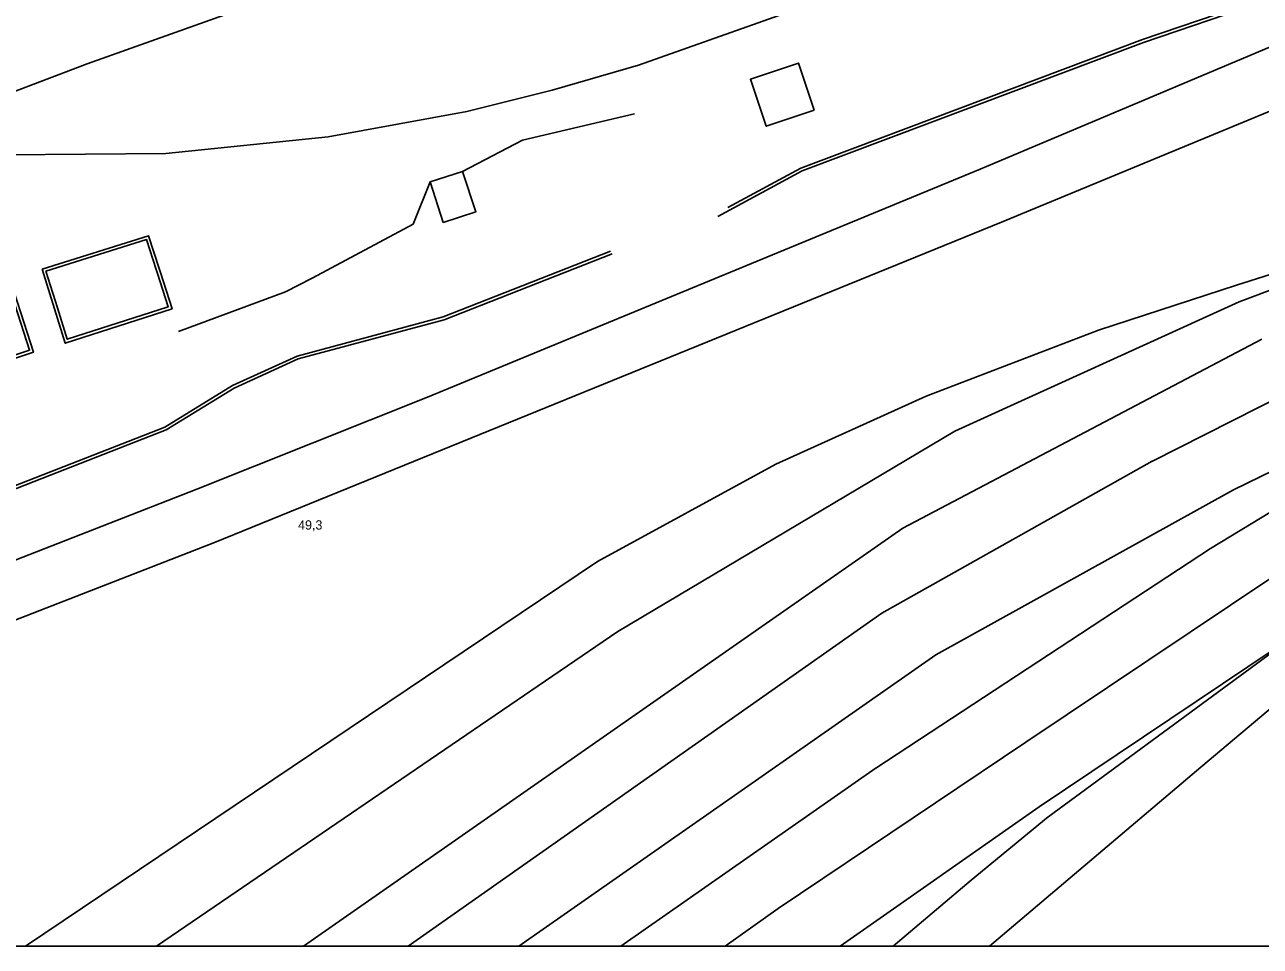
# Model space of a CAD drawing. Extents: x -932734 to -932083, y -737151 to -736752.
# Drawn here: x -932490.18 to -932480.24, y -736822.8 to -736815.38 of the extents above; entities that cross this region are included whole.
import ezdxf

# ---------------------------------------------------------------- set-up
doc = ezdxf.new("R2010")
doc.units = 0
for name, color, linetype in [('BorderBW', 7, 'Continuous'), ('Koleje_stávající', 7, 'Continuous'), ('Objekty_stávající', 7, 'Continuous'), ('SL_24_VODOVOD_PITNA', 7, 'Continuous'), ('WA_34_SCHODISTE', 7, 'Continuous'), ('WA_40_APARATY', 7, 'Continuous'), ('WA_46_TEXT', 7, 'Continuous')]:
    doc.layers.add(name, color=color, linetype=linetype)

# ---------------------------------------------------------------- blocks, each defined once
blk = doc.blocks.new('přehledka_1')
at = {"layer": 'BorderBW'}
for points in [[(0.07038371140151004, -0.048167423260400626), (0.07095589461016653, -0.050037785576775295), (0.06909275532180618, -0.05067112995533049), (0.06359666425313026, -0.05273965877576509), (0.06223989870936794, -0.053472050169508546)], [(0.06240033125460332, -0.053327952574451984), (0.063575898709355, -0.052694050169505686), (0.06907589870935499, -0.050624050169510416), (0.07089389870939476, -0.05000605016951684), (0.0703358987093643, -0.04818205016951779)], [(0.03090050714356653, -0.06521838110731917), (0.031617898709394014, -0.06500205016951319), (0.03645989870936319, -0.06340205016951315), (0.03973589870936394, -0.06237805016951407), (0.04277589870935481, -0.06099205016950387), (0.0433238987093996, -0.06076405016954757), (0.04648389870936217, -0.05954405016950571), (0.04893789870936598, -0.05858005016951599), (0.053337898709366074, -0.05686205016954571), (0.054429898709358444, -0.05619405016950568), (0.0554698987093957, -0.055718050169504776), (0.057817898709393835, -0.0550900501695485), (0.06051068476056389, -0.05402889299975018)], [(0.06054032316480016, -0.05407095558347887), (0.057833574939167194, -0.05513761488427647), (0.055486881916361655, -0.05576526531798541), (0.05445343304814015, -0.056238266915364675), (0.053360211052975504, -0.05690701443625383), (0.048956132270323, -0.05862660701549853), (0.046502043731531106, -0.05959064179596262), (0.04334250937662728, -0.06081046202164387), (0.04279587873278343, -0.06103789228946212), (0.03975379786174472, -0.06242484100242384), (0.03647520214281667, -0.0634496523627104), (0.03163296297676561, -0.06504973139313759), (0.031073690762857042, -0.06521838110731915)]]:
    blk.add_lwpolyline(points, dxfattribs=at)
at = {"layer": 'Koleje_stávající'}
for points in [[(0.05142461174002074, -0.05435464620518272), (0.051609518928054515, -0.054943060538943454), (0.05176850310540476, -0.05544901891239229), (0.05339300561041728, -0.05492577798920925), (0.05322057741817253, -0.05438935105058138), (0.05319975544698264, -0.05432454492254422), (0.05304550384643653, -0.05384465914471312)], [(0.0508118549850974, -0.05454069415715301), (0.05066389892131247, -0.05458770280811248), (0.04919491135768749, -0.05505449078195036), (0.04938414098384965, -0.05564069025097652), (0.04955197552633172, -0.05616065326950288), (0.05116111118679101, -0.055624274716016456), (0.050971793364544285, -0.0550374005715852)]]:
    blk.add_lwpolyline(points, close=True, dxfattribs=at)
at = {"layer": 'Objekty_stávající'}
for points in [[(0.03445734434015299, -0.06521838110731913), (0.036093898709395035, -0.06463005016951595), (0.04202189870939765, -0.06243405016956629), (0.0462318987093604, -0.06083805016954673), (0.053853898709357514, -0.05786005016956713), (0.057567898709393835, -0.05638005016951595), (0.06646389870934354, -0.05271205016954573), (0.07220389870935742, -0.050292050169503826), (0.07886789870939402, -0.04748005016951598), (0.0843098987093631, -0.045184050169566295), (0.08998389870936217, -0.042780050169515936), (0.0970738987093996, -0.03980405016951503), (0.09991516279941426, -0.03862719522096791)], [(0.03707951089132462, -0.06521838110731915), (0.0423098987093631, -0.06328005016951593), (0.0465698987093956, -0.06166605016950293), (0.05413589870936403, -0.05872005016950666), (0.06680589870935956, -0.053566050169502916), (0.07260589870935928, -0.05116405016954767), (0.0793358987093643, -0.04839405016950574), (0.08490189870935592, -0.04613605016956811), (0.09028589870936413, -0.044012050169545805), (0.0972998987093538, -0.041326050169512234), (0.09991516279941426, -0.0403290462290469)], [(0.04213989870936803, -0.05143205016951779), (0.04510189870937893, -0.05187005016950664), (0.04724389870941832, -0.05218205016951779), (0.050767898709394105, -0.05247805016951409), (0.05335589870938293, -0.052456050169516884), (0.05596989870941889, -0.05219005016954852), (0.05819789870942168, -0.0517840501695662), (0.0595738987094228, -0.051442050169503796), (0.060963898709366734, -0.05103605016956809), (0.06437789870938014, -0.049824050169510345), (0.06727189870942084, -0.048764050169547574), (0.07021389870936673, -0.04768805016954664)], [(0.08797569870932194, -0.04868965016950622), (0.08543629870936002, -0.04967485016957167), (0.0833004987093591, -0.05059485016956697), (0.07568049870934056, -0.05414905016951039), (0.06922669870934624, -0.05741405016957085)], [(0.08440069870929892, -0.05113105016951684), (0.08195849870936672, -0.05232105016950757), (0.07841649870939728, -0.05403305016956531), (0.07596669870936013, -0.055228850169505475), (0.07054209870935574, -0.057871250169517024), (0.06574909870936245, -0.06052825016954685), (0.05903593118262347, -0.06521838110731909)], [(0.08440069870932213, -0.05113105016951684), (0.08199049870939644, -0.052367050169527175), (0.0751196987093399, -0.056634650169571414), (0.06719969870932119, -0.06193325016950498)], [(0.07913069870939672, -0.051822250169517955), (0.07541009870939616, -0.05304845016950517), (0.07058929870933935, -0.054578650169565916)], [(0.0532065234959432, -0.06521838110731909), (0.06063189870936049, -0.06015325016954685), (0.06605249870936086, -0.05692725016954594), (0.07063089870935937, -0.05484865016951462), (0.07541009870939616, -0.05304845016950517)], [(0.05320652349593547, -0.0652183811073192), (0.06063189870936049, -0.06015325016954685), (0.06605249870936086, -0.05692725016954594), (0.07063089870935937, -0.05484865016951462), (0.07541009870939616, -0.05304845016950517)], [(0.05320652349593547, -0.0652183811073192), (0.06063189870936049, -0.06015325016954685), (0.06605249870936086, -0.05692725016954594), (0.07063089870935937, -0.05484865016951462), (0.07541009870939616, -0.05304845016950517)], [(0.07059029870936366, -0.0545784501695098), (0.0683656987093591, -0.055301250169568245), (0.06559509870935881, -0.05636445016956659), (0.0631758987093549, -0.05745645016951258), (0.060302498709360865, -0.0590228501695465), (0.051098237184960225, -0.06521838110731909)], [(0.07059029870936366, -0.0545784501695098), (0.0683656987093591, -0.05530125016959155), (0.06559509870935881, -0.0563644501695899), (0.0631758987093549, -0.05745645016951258), (0.060302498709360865, -0.0590228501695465), (0.05109823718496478, -0.06521838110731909)], [(0.07059029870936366, -0.0545784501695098), (0.0683656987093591, -0.05530125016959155), (0.06559509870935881, -0.0563644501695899), (0.0631758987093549, -0.05745645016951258), (0.060302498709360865, -0.0590228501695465), (0.05109823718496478, -0.06521838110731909)], [(0.07600629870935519, -0.055276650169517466), (0.07016849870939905, -0.05881525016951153), (0.06478249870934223, -0.06234985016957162)], [(0.07099469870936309, -0.05544885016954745), (0.0652186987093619, -0.058488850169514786), (0.05557305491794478, -0.06521838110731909)], [(0.07001209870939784, -0.06233385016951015), (0.0750636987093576, -0.05808785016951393), (0.07691129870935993, -0.05666765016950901)], [(0.057255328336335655, -0.0652183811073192), (0.0648784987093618, -0.059857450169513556), (0.0692320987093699, -0.05741105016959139)], [(0.06420773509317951, -0.06521838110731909), (0.0674128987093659, -0.06297625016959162), (0.07161789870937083, -0.06015305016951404)], [(0.07161789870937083, -0.06015305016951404), (0.0675508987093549, -0.06314165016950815)], [(0.06235853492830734, -0.0652183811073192), (0.06321049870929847, -0.06460925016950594), (0.067199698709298, -0.06193305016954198)], [(0.06067751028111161, -0.0652183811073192), (0.06478609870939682, -0.06234765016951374)], [(0.06661452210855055, -0.06521838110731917), (0.07001269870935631, -0.062333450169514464)], [(0.06755689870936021, -0.0631370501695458), (0.06631569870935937, -0.06415425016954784), (0.06506094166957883, -0.06521838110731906)]]:
    blk.add_lwpolyline(points, dxfattribs=at)
at = {"layer": 'WA_34_SCHODISTE'}
blk.add_lwpolyline([(0, 0), (0.09991516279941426, 0), (0.09991516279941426, -0.06521838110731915), (0, -0.06521838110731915)], close=True, dxfattribs=at)
at = {"layer": 'WA_40_APARATY'}
for points in [[(0.06379216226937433, -0.05176097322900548), (0.0635378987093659, -0.05100405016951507), (0.06276389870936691, -0.05126405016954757), (0.06301816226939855, -0.0520209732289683)], [(0.05781683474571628, -0.053569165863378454), (0.05760683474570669, -0.052917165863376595), (0.05813189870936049, -0.05274805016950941), (0.05834189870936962, -0.05340005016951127)]]:
    blk.add_lwpolyline(points, close=True, dxfattribs=at)
for points in [[(0.05136192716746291, -0.0543219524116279), (0.05156181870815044, -0.054958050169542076), (0.05173589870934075, -0.05551205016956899), (0.05345589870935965, -0.054958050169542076), (0.05326817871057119, -0.054374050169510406), (0.05324735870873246, -0.05430925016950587), (0.05307789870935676, -0.053782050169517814), (0.05136192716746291, -0.0543219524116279)], [(0.05084418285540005, -0.05447795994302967), (0.05064875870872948, -0.054540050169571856), (0.04913189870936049, -0.0550220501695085), (0.0493365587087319, -0.05565605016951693), (0.049519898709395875, -0.05622405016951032), (0.051223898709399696, -0.05565605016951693), (0.051019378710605, -0.0550220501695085), (0.05084418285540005, -0.05447795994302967)]]:
    blk.add_lwpolyline(points, dxfattribs=at)
at = {"layer": 'WA_46_TEXT'}
for points in [[(0.08627789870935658, -0.037758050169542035), (0.08363389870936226, -0.039394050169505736), (0.08224789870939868, -0.040084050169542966), (0.08155850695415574, -0.04037674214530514), (0.07831989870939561, -0.0412500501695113), (0.07529989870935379, -0.042404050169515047), (0.07174989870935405, -0.04376805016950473), (0.06721389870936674, -0.04551005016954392), (0.06387989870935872, -0.04677005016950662), (0.06302782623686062, -0.04706505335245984), (0.06120989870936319, -0.04773405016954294), (0.05674789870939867, -0.04935205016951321), (0.05208789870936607, -0.051014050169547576), (0.04977189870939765, -0.05189805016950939), (0.04848589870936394, -0.052330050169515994), (0.04734589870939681, -0.05270005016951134), (0.04302789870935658, -0.05413205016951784), (0.03886189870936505, -0.05539005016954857), (0.03673589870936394, -0.05607005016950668), (0.03664486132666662, -0.05610461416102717)], [(0.059096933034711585, -0.05224604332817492), (0.06089708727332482, -0.0518193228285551)], [(0.05760683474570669, -0.052917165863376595), (0.05813189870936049, -0.05274805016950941), (0.05909693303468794, -0.052246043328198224)], [(0.05355833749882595, -0.05532453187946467), (0.055279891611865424, -0.05468373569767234), (0.055711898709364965, -0.05446605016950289), (0.05733789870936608, -0.053594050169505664), (0.05760683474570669, -0.052917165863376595)]]:
    blk.add_lwpolyline(points, dxfattribs=at)
at = {"layer": 'Objekty_stávající'}
blk.add_text('49,3', height=0.00015000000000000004, dxfattribs=at).set_placement((0.05548389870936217, -0.058512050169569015))

msp = doc.modelspace()

# ---------------------------------------------------------------- block references
at = {"layer": 'SL_24_VODOVOD_PITNA', "xscale": 499.99957, "yscale": 499.99957}
msp.add_blockref('přehledka_1', (-932515.7231447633, -736790.1871344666), dxfattribs=at)

doc.saveas('drawing.dxf')
